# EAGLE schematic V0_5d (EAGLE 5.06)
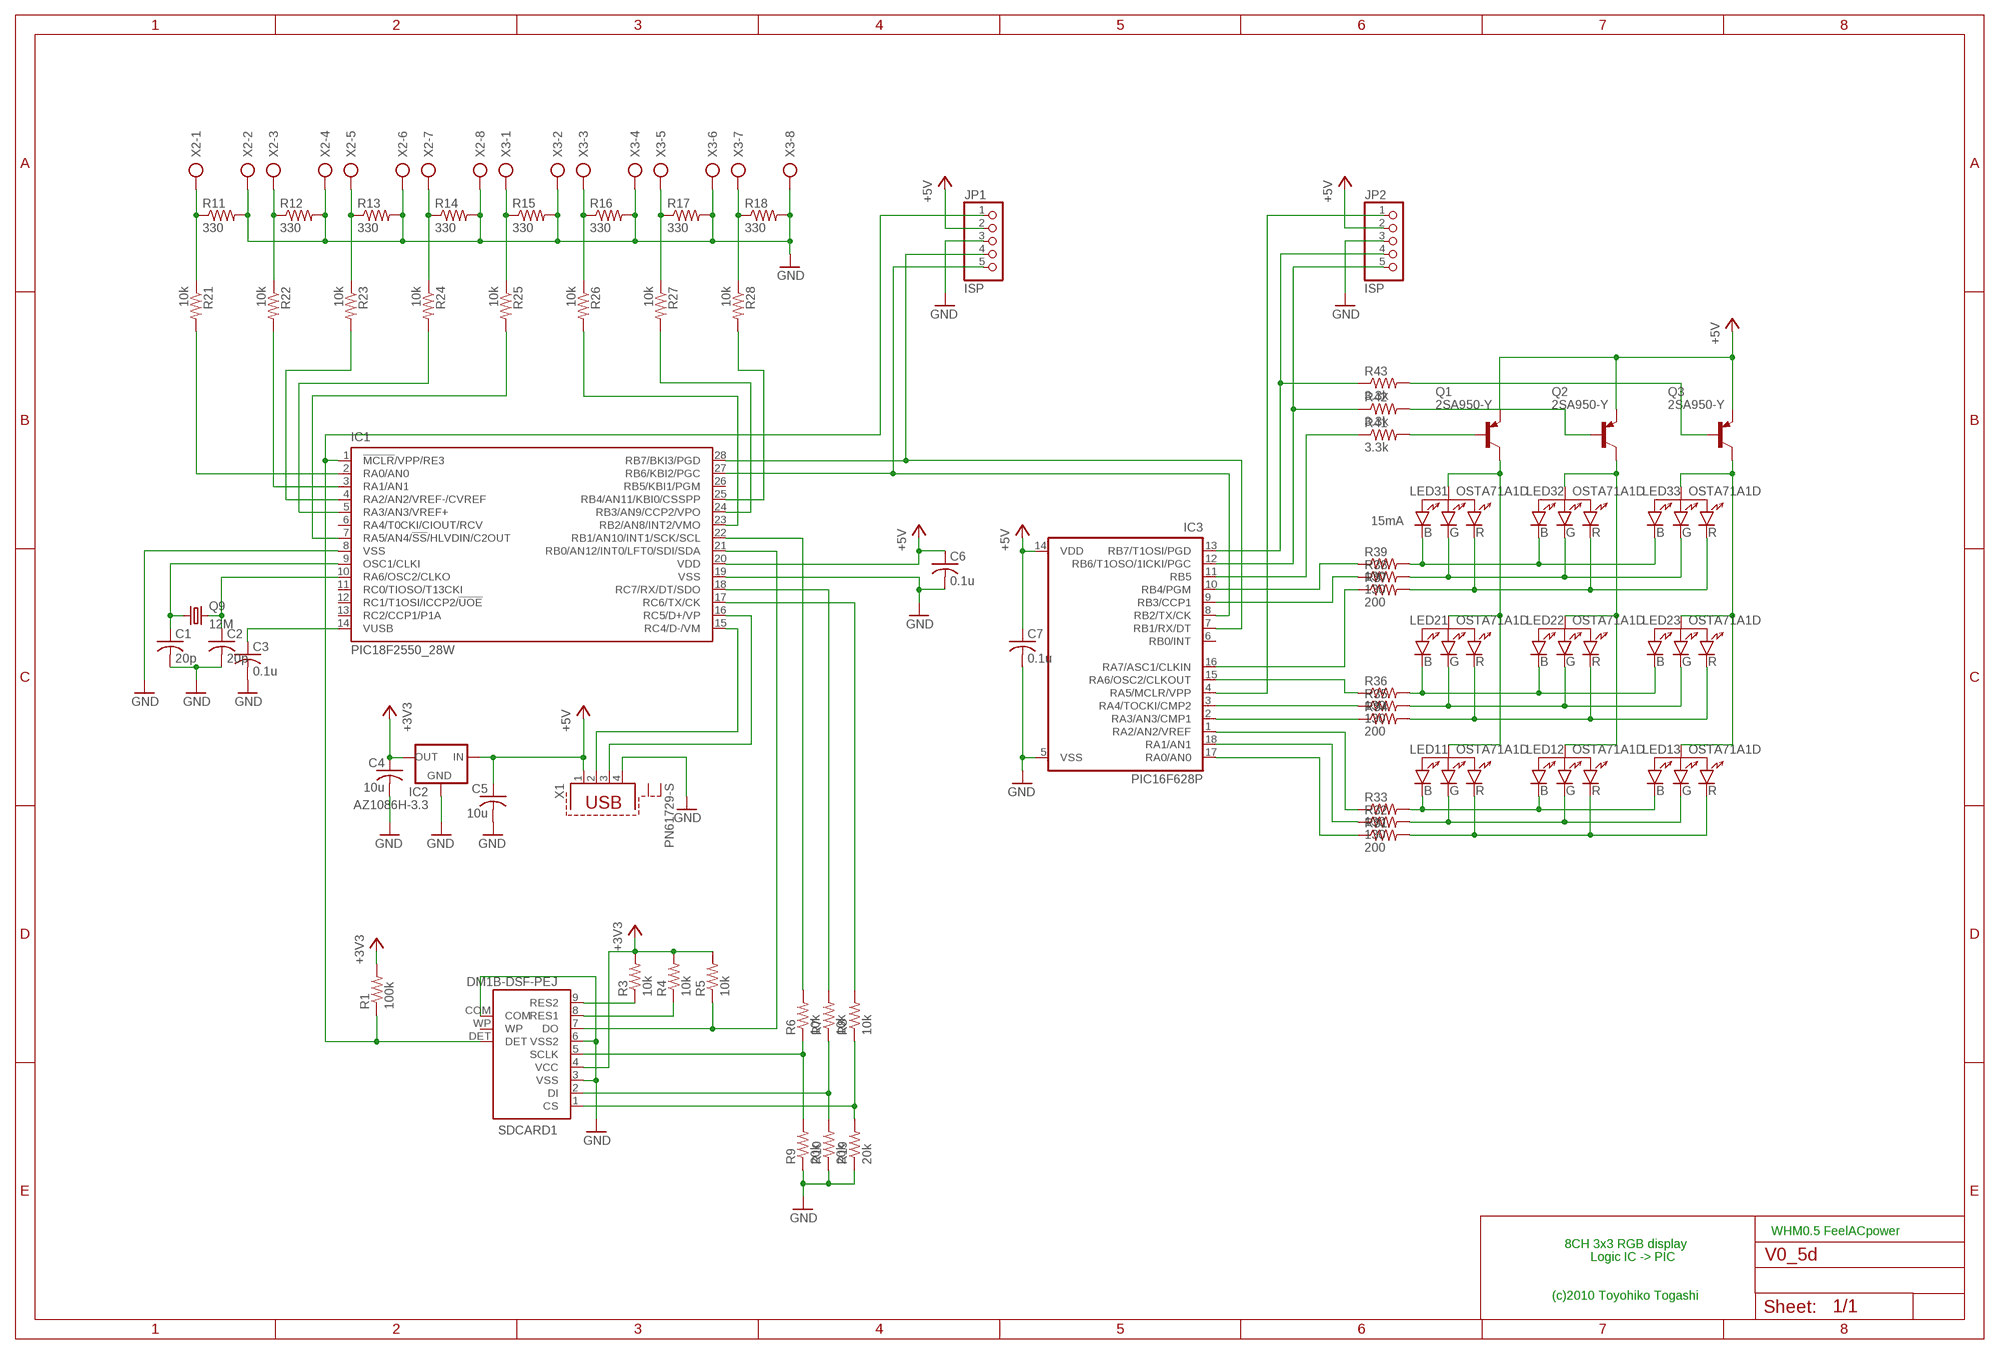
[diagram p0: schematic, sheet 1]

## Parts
C1  20p  C-US025-025X050  [C025-025X050]
C2  20p  C-US025-025X050  [C025-025X050]
C3  0.1u  C-US025-025X050  [C025-025X050]
C4  10u  C-US025-025X050  [C025-025X050]
C5  10u  C-US025-025X050  [C025-025X050]
C6  0.1u  C-US025-025X050  [C025-025X050]
C7  0.1u  C-USC0603  [C0603]
IC1  PIC18F2550_28W  [SO28W]
IC2  AZ1086H-3.3  XC63FPP  [SOT89R]
IC3  PIC16F628P  [DIL18]
JP1  ISP  PINHD-1X5  [1X05]
JP2  ISP  PINHD-1X5  [1X05]
LED11  OSTA71A1D  [FLUX-LED]
LED12  OSTA71A1D  [FLUX-LED]
LED13  OSTA71A1D  [FLUX-LED]
LED21  OSTA71A1D  [FLUX-LED]
LED22  OSTA71A1D  [FLUX-LED]
LED23  OSTA71A1D  [FLUX-LED]
LED31  OSTA71A1D  [FLUX-LED]
LED32  OSTA71A1D  [FLUX-LED]
LED33  OSTA71A1D  [FLUX-LED]
Q1  2SA950-Y  2N3906  [TO92]
Q2  2SA950-Y  2N3906  [TO92]
Q3  2SA950-Y  2N3906  [TO92]
Q9  12M  CRYSTALHC49S  [HC49/S]
R1  100k  R-US_0207/7  [0207/7]
R3  10k  R-US_0207/7  [0207/7]
R4  10k  R-US_0207/7  [0207/7]
R5  10k  R-US_0207/7  [0207/7]
R6  10k  R-US_0207/7  [0207/7]
R7  10k  R-US_0207/7  [0207/7]
R8  10k  R-US_0207/7  [0207/7]
R9  20k  R-US_0207/7  [0207/7]
R10  20k  R-US_0207/7  [0207/7]
R11  330  R-US_0207/7  [0207/7]
R12  330  R-US_0207/7  [0207/7]
R13  330  R-US_0207/7  [0207/7]
R14  330  R-US_0207/7  [0207/7]
R15  330  R-US_0207/7  [0207/7]
R16  330  R-US_0207/7  [0207/7]
R17  330  R-US_0207/7  [0207/7]
R18  330  R-US_0207/7  [0207/7]
R19  20k  R-US_0207/7  [0207/7]
R21  10k  R-US_0207/7  [0207/7]
R22  10k  R-US_0207/7  [0207/7]
R23  10k  R-US_0207/7  [0207/7]
R24  10k  R-US_0207/7  [0207/7]
R25  10k  R-US_0207/7  [0207/7]
R26  10k  R-US_0207/7  [0207/7]
R27  10k  R-US_0207/7  [0207/7]
R28  10k  R-US_0207/7  [0207/7]
R31  200  R-US_0207/7  [0207/7]
R32  130  R-US_0207/7  [0207/7]
R33  130  R-US_0207/7  [0207/7]
R34  200  R-US_0207/7  [0207/7]
R35  130  R-US_0207/7  [0207/7]
R36  130  R-US_0207/7  [0207/7]
R37  200  R-US_0207/7  [0207/7]
R38  130  R-US_0207/7  [0207/7]
R39  130  R-US_0207/7  [0207/7]
R41  3.3k  R-US_0207/7  [0207/7]
R42  3.3k  R-US_0207/7  [0207/7]
R43  3.3k  R-US_0207/7  [0207/7]
SDCARD1  DM1B-DSF-PEJ  [DM1B]
X1  PN61729-S  [PN61729-S]
X2  AK500/8  [AK500/8]
X3  AK500/8  [AK500/8]

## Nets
+3V3: C4.1 IC2.3(OUT) R1.2 R3.2 R4.2 R5.2 SDCARD1.4(VCC)
+5V: C5.1 C6.1 C7.1 IC1.20(VDD) IC2.2(IN) IC3.14(VDD) JP1.2 JP2.2 Q1.3(E) Q2.3(E) Q3.3(E) X1.1
GND: C1.2 C2.2 C3.2 C4.2 C5.2 C6.2 C7.2 IC1.8(VSS) IC1.19(VSS) IC2.1(GND) IC3.5(VSS) JP1.3 JP2.3 R9.1 R10.1 R11.2 R12.2 R13.2 R14.2 R15.2 R16.2 R17.2 R18.2 R19.1 SDCARD1.3(VSS) SDCARD1.6(VSS2) SDCARD1.COM X2.2 X2.4 X2.6 X2.8 X3.2 X3.4 X3.6 X3.8
N$1: IC1.7(RA5/AN4/!SS!/HLVDIN/C2OUT) R25.2
N$2: IC1.5(RA3/AN3/VREF+) R24.2
N$3: IC1.4(RA2/AN2/VREF-/CVREF) R23.2
N$4: IC1.3(RA1/AN1) R22.2
N$5: R18.1 R28.1 X3.7
N$6: R6.1 R9.2 SDCARD1.5(SCLK)
N$7: IC1.21(RB0/AN12/INT0/LFT0/SDI/SDA) R5.1 SDCARD1.7(DO)
N$8: R7.1 R10.2 SDCARD1.2(DI)
N$9: R8.1 R19.2 SDCARD1.1(CS)
N$10: IC1.1(!MCLR!/VPP/RE3) JP1.1 R1.1 SDCARD1.DET
N$11: LED11.P$2 LED12.P$2 LED13.P$2 R33.2
N$12: LED11.P$3 LED12.P$3 LED13.P$3 R32.2
N$13: LED11.P$4 LED12.P$4 LED13.P$4 R31.2
N$14: IC3.13(RB7/T1OSI/PGD) JP2.4 R43.1
N$15: LED12.P$1 LED22.P$1 LED32.P$1 Q2.1(C)
N$16: IC1.15(RC4/D-/VM) X1.2
N$18: LED13.P$1 LED23.P$1 LED33.P$1 Q3.1(C)
N$19: IC1.16(RC5/D+/VP) X1.3
N$20: IC1.22(RB1/AN10/INT1/SCK/SCL) R6.2
N$21: IC1.18(RC7/RX/DT/SDO) R7.2
N$22: IC1.17(RC6/TX/CK) R8.2
N$23: IC3.11(RB5) R41.1
N$25: IC3.17(RA0/AN0) R31.1
N$26: IC3.4(RA5/MCLR/VPP) JP2.1
N$27: IC3.18(RA1/AN1) R32.1
N$28: IC3.1(RA2/AN2/VREF) R33.1
N$29: IC1.23(RB2/AN8/INT2/VMO) R26.2
N$30: IC1.28(RB7/BKI3/PGD) IC3.7(RB1/RX/DT) JP1.4
N$31: IC1.27(RB6/KBI2/PGC) IC3.8(RB2/TX/CK) JP1.5
N$32: IC1.24(RB3/AN9/CCP2/VPO) R27.2
N$33: Q1.2(B) R41.2
N$34: IC1.25(RB4/AN11/KBI0/CSSPP) R28.2
N$35: Q2.2(B) R42.2
N$36: R17.1 R27.1 X3.5
N$37: R16.1 R26.1 X3.3
N$38: R15.1 R25.1 X3.1
N$39: R14.1 R24.1 X2.7
N$40: R13.1 R23.1 X2.5
N$41: R12.1 R22.1 X2.3
N$42: R3.1 SDCARD1.9(RES2)
N$43: R4.1 SDCARD1.8(RES1)
N$44: R11.1 R21.1 X2.1
N$45: Q3.2(B) R43.2
N$46: IC3.2(RA3/AN3/CMP1) R34.1
N$47: C2.1 IC1.10(RA6/OSC2/CLKO) Q9.2
N$49: C1.1 IC1.9(OSC1/CLKI) Q9.1
N$50: IC1.2(RA0/AN0) R21.2
N$51: LED31.P$2 LED32.P$2 LED33.P$2 R39.2
N$52: C3.1 IC1.14(VUSB)
N$53: LED31.P$3 LED32.P$3 LED33.P$3 R38.2
N$54: LED31.P$4 LED32.P$4 LED33.P$4 R37.2
N$55: LED11.P$1 LED31.P$1 Q1.1(C)
N$56: LED21.P$2 LED22.P$2 LED23.P$2 R36.2
N$57: LED21.P$3 LED22.P$3 LED23.P$3 R35.2
N$58: LED21.P$4 LED22.P$4 LED23.P$4 R34.2
N$59: IC3.3(RA4/TOCKI/CMP2) R35.1
N$60: IC3.15(RA6/OSC2/CLKOUT) R36.1
N$61: IC3.16(RA7/ASC1/CLKIN) R37.1
N$62: IC3.9(RB3/CCP1) R38.1
N$64: IC3.10(RB4/PGM) R39.1
N$65: IC3.12(RB6/T1OSO/1ICKI/PGC) JP2.5 R42.1
Unconnected: IC1.6(RA4/T0CKI/CIOUT/RCV) IC1.11(RC0/TIOSO/T13CKI) IC1.12(RC1/T1OSI/ICCP2/!UOE) IC1.13(RC2/CCP1/P1A) IC1.26(RB5/KBI1/PGM) IC3.6(RB0/INT) LED21.P$1 SDCARD1.WP X1.4 X1.S1 X1.S2

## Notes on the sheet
- 15mA
- WHM0.5 FeelACpower
- 8CH 3x3 RGB display
- Logic IC -> PIC
- (c)2010 Toyohiko Togashi

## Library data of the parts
C1-C7 = rcl:C-US: CAPACITOR, American symbol
IC1 = microchip:PIC18F2*_28: USB Microcontrollers with nanoWatt Technology High-Performance, Enhanced Flash, 28/40/44-Pin, Source: http://ww1.microchip.com/downloads/en/devicedoc/39632c.pdf
IC2 = v-reg:XC63FP: Positiv Voltage Regulators www.torex.co.jp/english/product/pro02/pdf/0201_xc62fp.pdf
IC3 = microchip:PIC16*F62: FLASH-Based 8-Bit CMOS Microcontroller Source: http://ww1.microchip.com/downloads/en/DeviceDoc/40300C.pdf
JP1 JP2 = pinhead:PINHD-1X5: PIN HEADER
LED11-LED13 LED21-LED23 LED31-LED33 = TOG:OSTA71A1D: Super Flux RGB LED
Q1-Q3 = transistor-pnp:2N3906: PNP Transistor
Q9 = crystal:CRYSTAL: CRYSTAL
R1 R3-R19 R21-R28 R31-R39 R41-R43 = rcl:R-US_: RESISTOR, American symbol
SDCARD1 = TOG:DM1B-DSF-PEJ: SDcard connector reverse type HIROSE
X1 = con-berg:PN61729-S: BERG USB connector
X2 X3 = con-ptr500:AK500/8: CONNECTOR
